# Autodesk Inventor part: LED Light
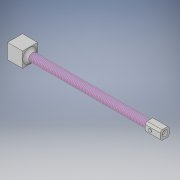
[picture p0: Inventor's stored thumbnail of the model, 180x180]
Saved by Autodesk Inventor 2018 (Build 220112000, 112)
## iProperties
Created: 2017-07
Part Number: LED Light
Material: Generic
Document SubType Name: Modeling
Designer: 17046589
Density: 1 g/cm^3
Appearance: Default
Author: 17046589
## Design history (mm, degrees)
sketch "Sketch1"
  geometry: L1 (0, 0)-(-10, 0); L2 (-10, 0)-(-10, -10); L3 (-10, -10)-(0, -10); L4 (0, -10)-(0, 0)
  constraints: 8 end point, 3 perpendicular, 1 horizontal
  dimensions: "d0" = 10 distance of L1.start L1.end; "d1" = 10 distance of L1.end L2.end
extrude "Extrusion1" new body sketch "Sketch1" distance "d2" = 10; taper "d3" = 0 deg
sketch "Sketch2"
  geometry: C1 r 2.655 at (4.786, -4.856); 1 further point
  constraints: 1 centre point
extrude "Extrusion2" join sketch "Sketch2" distance "d4" = 80; taper "d5" = 0 deg
sketch "Sketch3"
  geometry: L1 (-3.019, 2.862)-(3.327, 2.862); L2 (3.327, 2.862)-(3.327, -3.302); L3 (3.327, -3.302)-(-3.019, -3.302); L4 (-3.019, -3.302)-(-3.019, 2.862); 1 further point
  constraints: 8 end point, 2 parallel, 1 horizontal, 1 perpendicular
extrude "Extrusion3" join sketch "Sketch3" distance "d6" = 10; taper "d7" = 0 deg
chamfer "Chamfer1" distance "d8" = 1.25; stored, may be unused: second distance "d9" = 1.25, angle "d10" = 45 deg
chamfer "Chamfer2" distance "d11" = 1.25; stored, may be unused: second distance "d12" = 1.25, angle "d13" = 45 deg
hole "Hole1" diameter "d16" = 2; stored, may be unused: countersink angle "d20" = 90 deg, drill point angle "d22" = 118 deg; dims "d14" = 10, "d15" = 10, "d17" = 7.5, "d18" = 3.75, "d19" = 2.5, "d21" = 7.925
hole "Hole2" diameter "d25" = 2; stored, may be unused: countersink angle "d29" = 90 deg, drill point angle "d31" = 118 deg; dims "d23" = 10, "d24" = 10, "d26" = 7.5, "d27" = 3.75, "d28" = 2.5, "d30" = 7.925
fillet "Fillet1" dims "d32" = 2
thread "Thread1" dims "d33" = 10, "d34" = 0
sketch "Sketch4"
  geometry: C1 r 1.017 at (3.493, -1.709); 1 further point
  constraints: 1 centre point
extrude "Extrusion4" join sketch "Sketch4" distance "d35" = 0.4; taper "d36" = 0 deg
body "Solid1"
